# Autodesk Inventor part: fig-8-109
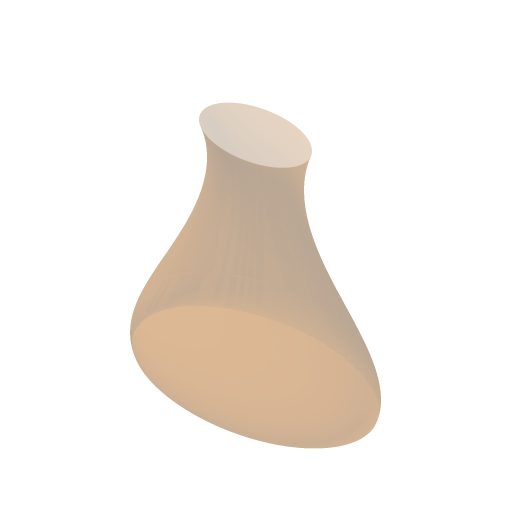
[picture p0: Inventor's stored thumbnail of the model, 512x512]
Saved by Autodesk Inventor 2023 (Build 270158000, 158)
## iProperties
Created: 2004-05
Part Number: fig-8-109
Document SubType Name: Modeling
Designer: CADCIM Technologies
Manufacturer: Standard
Standards Organization: Custom
Density: 1 g/cm^3
Material: Generic
Appearance: Default
Author: CADCIM Technologies
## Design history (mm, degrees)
sketch "Sketch4"
  geometry: 1 further point; 1 other entity
  constraints: 2 other
workplane "Work Plane2"
sketch "Sketch5"
  geometry: 1 further point; 1 other entity
  constraints: 2 other
feature "LoftSrf1" sketch "Sketch5" dims "d4" = 20, "d5" = 110 deg, "d6" = 40, "d7" = 70 deg
patch "Boundary Patch1" dims "d8" = 0, "d9" = 0
body "Srf1"
body "Srf2"
other parameters: "d3" = 33.5
